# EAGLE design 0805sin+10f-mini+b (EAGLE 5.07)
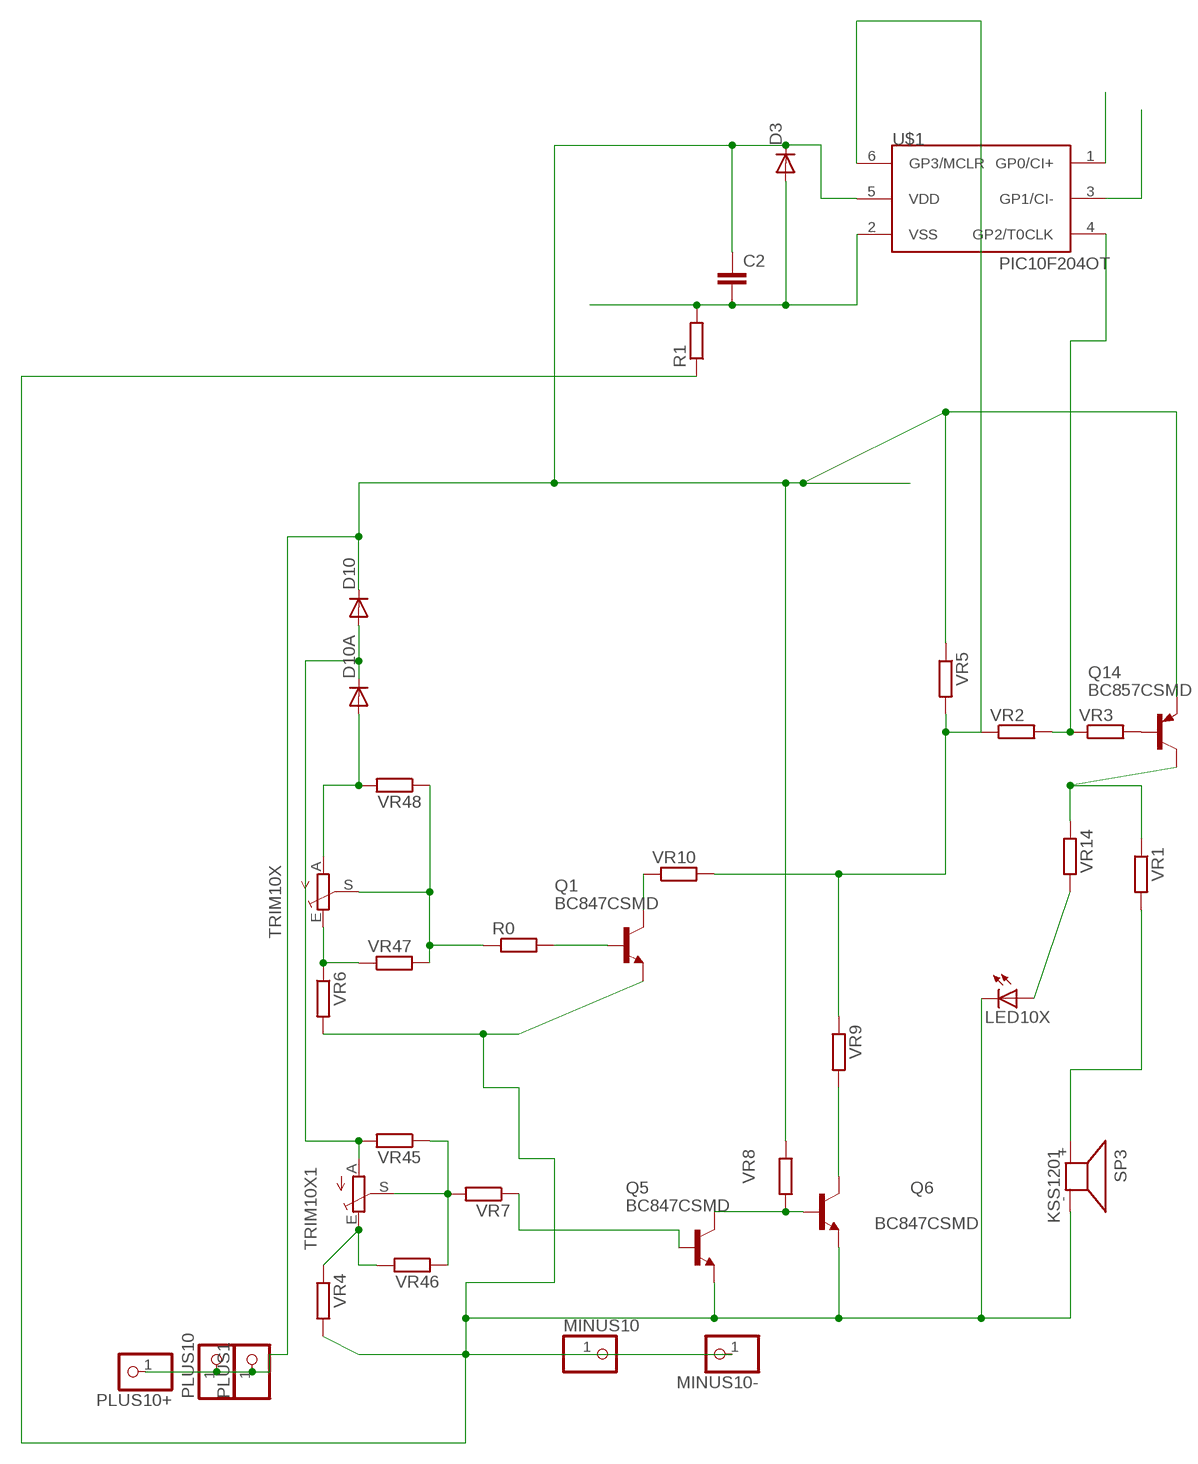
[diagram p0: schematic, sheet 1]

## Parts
C2  C-EUC0805  [C0805]
D3  DIODE-MINIMELF  [MINIMELF]
D10  DIODE-MINIMELF  [MINIMELF]
D10A  DIODE-MINIMELF  [MINIMELF]
LED10X  LEDCHIPLED_1206  [CHIPLED_1206]
MINUS10  PINHD-1X14.5MM  [1X4MM5]
MINUS10-  PINHD-1X11X0.4  [1X01]
PLUS1  PINHD-1X14.5MM  [1X4MM5]
PLUS10  PINHD-1X14.5MM  [1X4MM5]
PLUS10+  PINHD-1X11X0.4  [1X01]
Q1  BC847CSMD  [SOT23]
Q5  BC847CSMD  [SOT23]
Q6  BC847CSMD  [SOT23]
Q14  BC857CSMD  [SOT23-BEC]
R0  R-EU_R0805  [R0805]
R1  R-EU_R0805  [R0805]
SP3  KSS1201  KSS12017MM  [KSS1202]
TRIM10X  TRIM_EU-S64W  [S64W]
TRIM10X1  TRIM_EU-S64W  [S64W]
U$1  PIC10F204OT  [SOT23-6]
VR1  R-EU_R0805  [R0805]
VR2  R-EU_R0805  [R0805]
VR3  R-EU_R1206  [R1206]
VR4  R-EU_R1206  [R1206]
VR5  R-EU_R0805  [R0805]
VR6  R-EU_R1206  [R1206]
VR7  R-EU_M1206  [M1206]
VR8  R-EU_R1206  [R1206]
VR9  R-EU_R0805  [R0805]
VR10  R-EU_R1206  [R1206]
VR14  R-EU_R0805  [R0805]
VR45  R-EU_R1206  [R1206]
VR46  R-EU_R0805  [R0805]
VR47  R-EU_R0805  [R0805]
VR48  R-EU_R0805  [R0805]

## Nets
B: R0.1 TRIM10X.S VR47.2 VR48.1
GP3: U$1.4(GP2/T0CLK) VR2.2 VR3.1
N$1: SP3.+ VR1.2
N$2: Q1.3(C) VR10.1
N$3: Q5.3(C) Q6.1(B) VR8.2
N$4: LED10X.A VR14.2
N$5: Q6.3(C) VR9.2
N$6: U$1.6(GP3/MCLR) VR2.1 VR5.2 VR9.1 VR10.2
N$7: Q1.1(B) R0.2
N$8: Q14.C VR1.1 VR14.1
N$10: Q14.B VR3.2
N$14: D10A.A TRIM10X.A VR48.2
N$17: D10.A D10A.C TRIM10X1.A VR45.2
N$22: TRIM10X1.S VR7.2 VR45.1 VR46.1
N$24: TRIM10X1.E VR4.1 VR46.2
N$128: TRIM10X.E VR6.1 VR47.1
N$138: U$1.1(GP0/CI+)
N$165: U$1.3(GP1/CI-)
N$168: Q5.1(B) VR7.1
PLUS11: C2.1 D3.C D10.C PLUS1.1 PLUS10+.1 PLUS10.1 Q14.E U$1.5(VDD) VR5.1 VR8.1
VSS: LED10X.C MINUS10-.1 MINUS10.1 Q1.2(E) Q5.2(E) Q6.2(E) R1.1 SP3.- VR4.2 VR6.2
VSS1: C2.2 D3.A R1.2 U$1.2(VSS)

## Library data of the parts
C2 = rcl:C-EU: CAPACITOR, European symbol
D3 D10 D10A = diode:DIODE-: DIODE
LED10X = led:LED: LED
MINUS10 MINUS10- PLUS1 PLUS10 PLUS10+ = pinhead:PINHD-1X1: PIN HEADER
Q1 Q5 Q6 = transistor-npn:BC847*: NPN Transistor
Q14 = transistor-pnp:BC857*: PNP Transistror
R0 R1 VR1-VR10 VR14 VR45-VR48 = rcl-2:R-EU_: RESISTOR, European symbol
SP3 = buzzer:KSS1201: SPEAKER
TRIM10X TRIM10X1 = pot:TRIM_EU-: POTENTIOMETER
U$1 = microchip-3:PIC10F2*: uPC nW 0,25/0,5k Program Flash memory Comparator

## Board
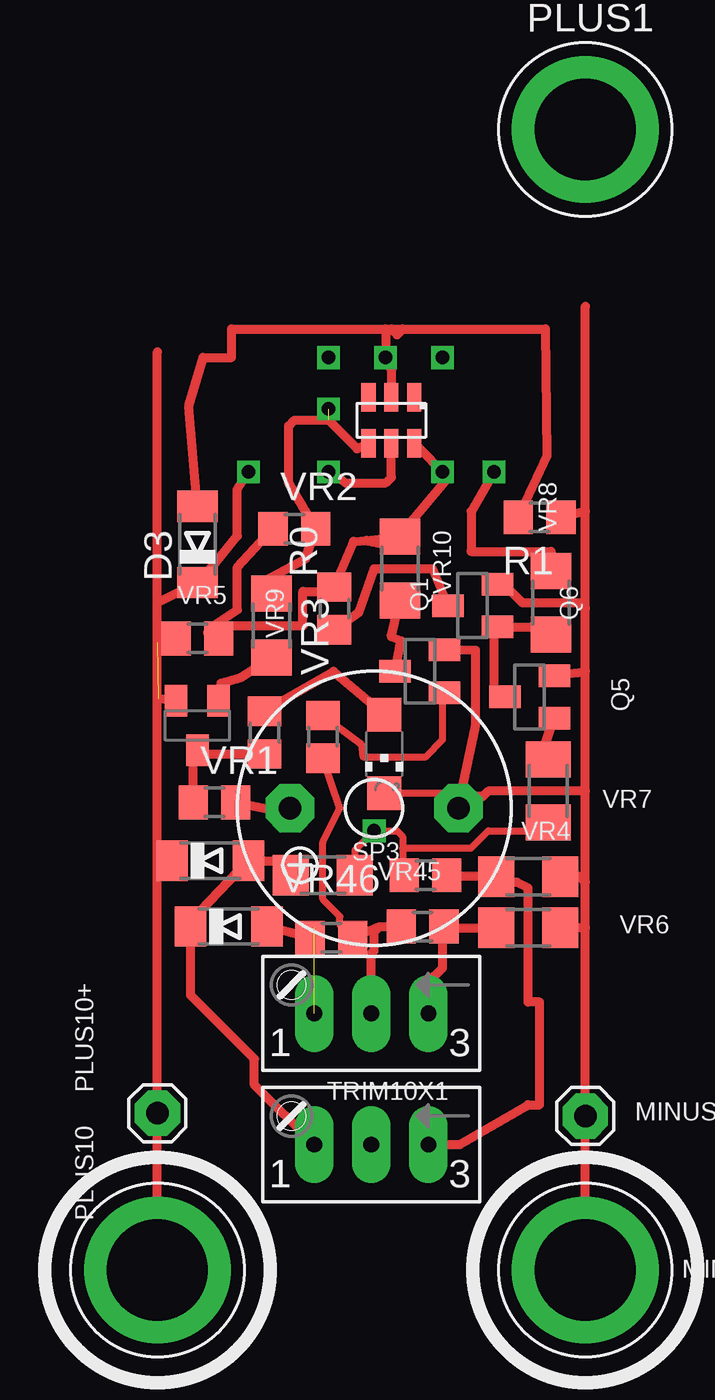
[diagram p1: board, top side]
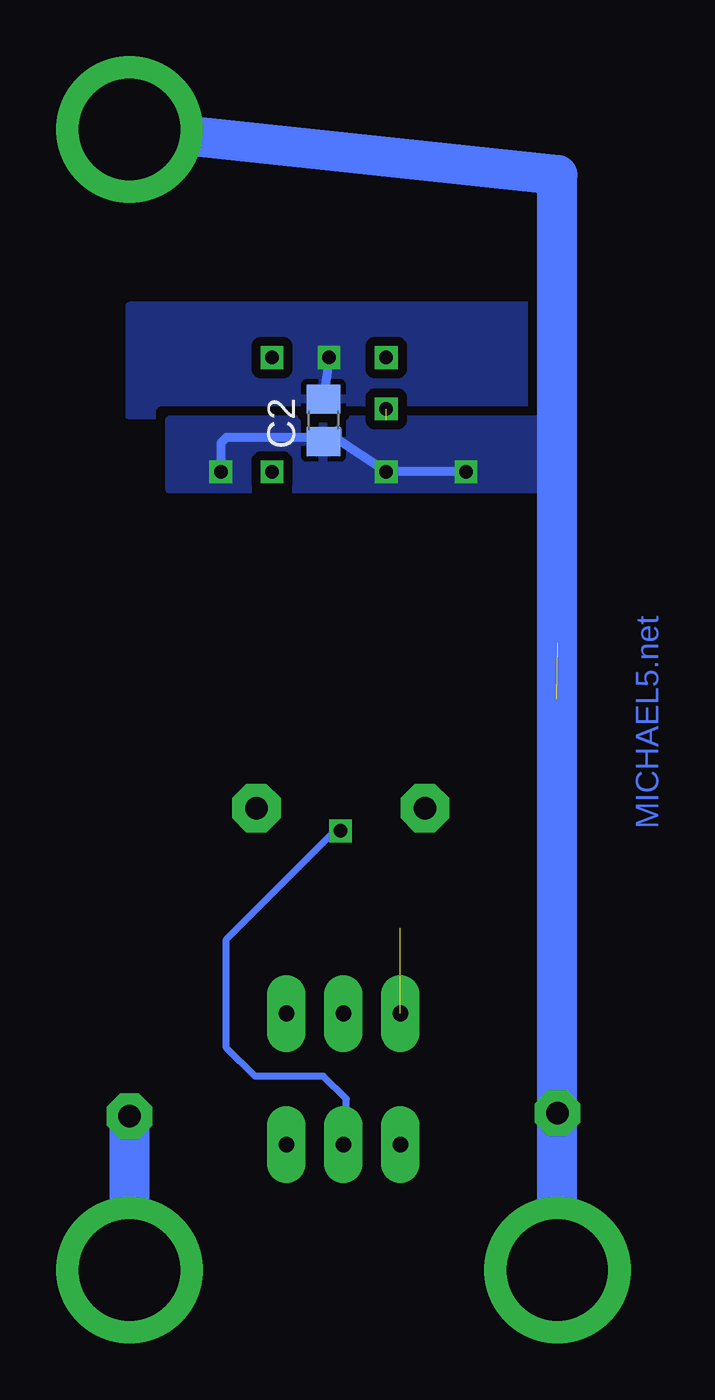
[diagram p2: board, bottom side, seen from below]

No outline drawn. Coordinates in mm, seen from the top.
Copper layers (1*16): Top 0.035mm / dielectric 1.5mm / Bottom 0.035mm
Design rules "default *": minimum track width 8mil, minimum drill 4mil, track to track 8mil, track to pad 8mil, pad to pad 8mil, via to via 8mil, smd to smd 8mil, copper to edge 40mil, drill to drill 8mil, minimum pad ring 20mil, minimum via ring 8mil, stop-mask expansion 4mil, vias tented up to drill 0mil, thermal gap 10mil

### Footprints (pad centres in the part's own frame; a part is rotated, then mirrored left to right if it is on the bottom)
C0805 = smd 1.3 x 1.5: 1 -0.95,0; 2 0.95,0
MINIMELF = smd 1.4 x 1.8: A 1.7,0; C -1.7,0
CHIPLED_1206 = smd 1.5 x 1.5: A 0,-1.75; C 0,1.75
1X4MM5 = drill 4.5 pad 6.35 round: 1 0,0
1X01 = drill 1 pad 1.676 octagon: 1 0,0
SOT23 = smd 1 x 1.4: 1 -0.95,-1.1; 2 0.95,-1.1; 3 0,1.1
SOT23-BEC = smd 1 x 1.4: B -0.95,-1.1; C 0,1.1; E 0.95,-1.1
R0805 = smd 1.3 x 1.5: 1 -0.95,0; 2 0.95,0
KSS1202 = drill 1 pad 2.159 octagon: + 3.75,0; - -3.75,0
S64W = drill 0.7 long: A 2.54,1.27; E -2.54,1.27; S 0,1.27
SOT23-6 = smd 0.635 x 1.27: 1 -1.016,-1.016; 2 0,-1.016; 3 1.016,-1.016; 4 1.016,1.016; 5 0,1.016; 6 -1.016,1.016
R1206 = smd 1.6 x 1.803: 1 -1.422,0; 2 1.422,0
M1206 = smd 1.6 x 2: 1 -1.4,0; 2 1.4,0

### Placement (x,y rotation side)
C2  81.53,46.74 90 bottom
D3  72.9,41.21 90 top
D10  73.47,27.11 0 top
D10A  74.3,24.19 0 top
LED10X  81.22,31.88 180 top
MINUS10  90.17,8.89 0 top
MINUS10-  90.17,15.75 0 top
PLUS1  90.17,59.69 0 top
PLUS10  71.12,8.89 0 top
PLUS10+  71.12,15.88 0 top
Q1  82.8,35.56 90 top
Q5  87.69,34.42 90 top
Q6  85.15,38.48 90 top
Q14  72.9,33.15 180 top
R0  78.49,32.64 90 top
R1  88.14,42.42 180 top
SP3  80.77,29.46 180 top
TRIM10X  80.64,21.59 180 top
TRIM10X1  80.64,15.75 180 top
U$1  81.53,46.74 180 top
VR1  73.66,29.72 0 top
VR2  77.22,41.91 0 top
VR3  76.2,37.59 270 top
VR4  87.63,26.42 0 top
VR5  72.9,37.02 0 top
VR6  87.63,24.13 0 top
VR7  88.52,30.23 270 top
VR8  88.65,38.61 270 top
VR9  78.99,38.35 270 top
VR10  81.92,40.13 90 top
VR14  75.88,32.83 90 top
VR45  78.49,26.48 180 top
VR46  83.06,26.48 0 top
VR47  82.93,24.19 180 top
VR48  78.87,23.69 180 top

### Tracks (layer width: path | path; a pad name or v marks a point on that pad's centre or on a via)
B
  Top 0.305: R0.1 79.25,29.46 78.49,27.94 78.49,25.4 79.25,24.64 79.25,24.25 VR48.1
  Top 0.406: 81.03,24.19 VR48.1 | 81.03,24.19 VR47.2 | TRIM10X.S 80.64,22.99 80.77,23.11 80.77,23.94 81.03,24.19
GP3  (via drill 0.6)  (1 unrouted)
  Top 0.406: U$1.4 80.01,45.47 78.74,46.74 77.22,46.74 76.96,46.48 76.96,43.94 VR2.2 77.72,40.57 75.95,39.62 76.2,39.37 VR3.1
  other vias: 78.74,47.24
N$1
  Top 0.406: VR1.2 76.83,29.28 SP3.+
N$2
  Top 0.406: Q1.3 81.96,36.91 81.53,37.08 VR10.1
N$3
  Top 0.406: Q5.3 86.11,34.78 86.11,37.53 Q6.1 88.3,37.53 VR8.2
N$4
  Top 0.406: VR14.2 78.96,35.56 LED10X.A
N$5
  Top 0.406: VR9.2 80.08,38.17 80.77,40.13 83.36,40.13 Q6.3
N$6
  Top 0.406: U$1.6 84.07,44.2 81.53,41.15 80.42,41.39 | 80.42,41.39 VR10.2 | VR5.2 73.34,37.27 73.66,37.59 | 73.66,37.59 77.6,37.59 77.6,39.12 78.67,39.12 VR9.1 79.86,41.34 80.42,41.39 | VR2.1 74.68,40.2 74.68,38.29 73.66,37.59
N$7
  Top 0.305: R0.2 80.2,32.32 80.26,31.75 83.06,31.75 83.82,32.51 83.82,34.53 Q1.1
N$8
  Top 0.406: VR14.1 73.07,31.88 Q14.C 72.71,31.86 VR1.1
N$9  (via drill 0.6)
  other vias: 83.82,44.45
N$10
  Top 0.406: Q14.B 73.96,35.03 74.84,35.28 VR3.2
N$11  (via drill 0.6)
  other vias: 83.82,49.53
N$14  (1 unrouted)
  Top 0.406: 78.11,24.13 VR48.2 D10A.A
N$17
  Top 0.406: VR45.2 77.6,27.11 D10.A 72.59,24.41 D10A.C 72.59,21.13 75.44,18.29 75.44,17.14 TRIM10X1.A
N$22  (via drill 0.6)
  Top 0.305: VR46.1 82.04,26.48 82.04,27.69 | 82.04,27.69 85.09,27.69 85.85,28.45 88.14,28.45 VR7.2 | VR45.1 79.91,27.58 v80.77,28.45 81.79,28.45 82.04,28.19 82.04,27.69
  Bottom 0.305: v80.77,28.45 81.03,28.45 85.85,23.62 85.85,18.8 84.58,17.53 81.53,17.53 80.52,16.51 80.52,14.61 TRIM10X1.S
N$24
  Top 0.406: TRIM10X1.E 84.58,14.48 87.63,16.26 88.14,16.26 88.14,20.83 87.63,20.83 87.63,25.91 87.12,26.16 86.46,26.16 VR4.1 84.03,26.42 VR46.2
N$128
  Top 0.406: TRIM10X.E 83.19,21.72 83.82,22.35 83.82,24.13 VR47.1 83.82,24.13 VR6.1
N$168
  Top 0.406: Q5.1 88.28,31.99 VR7.1
PLUS11  (via drill 0.6)  (1 unrouted)
  Top 0.406: PLUS10.1 71.12,27.11 | 71.12,27.11 D10.C | Q14.E 71.16,34.33 | VR8.1 88.65,40.89 85.09,40.89 85.09,42.67 v86.11,44.45 | U$1.5 81.53,44.2 81.28,43.94 79.5,43.94 v78.74,44.45 | v75.18,44.45 74.68,43.69 74.68,41.59 73.6,40.26 D3.C 71.12,38.62 | 71.12,27.11 71.12,36.83 | 71.12,36.83 71.12,38.62 | 71.12,38.62 71.12,49.78 | VR5.1 71.31,37.02 71.12,36.83
  Bottom 0.406: v86.11,44.45 86.11,45.72 85.85,45.97 81.03,45.97 | 81.03,45.97 v78.74,44.45 v75.18,44.45 | C2.1 80.91,46.29 80.91,45.9 81.03,45.9 81.03,45.97
  Bottom 1.778: PLUS1.1 71.12,57.66 PLUS10+.1 PLUS10.1
  pour Bottom (isolate 0.406): 70.61,46.74 88.39,46.74 88.39,43.69 70.87,43.69
VDF  (via drill 0.6)
  other vias: 78.74,49.53
VSS
  Top 0.305: LED10X.C 83.86,30.13 SP3.-
  Top 0.406: 90.17,30.23 90.17,35.56 | 90.17,35.56 90.17,38.35 | 90.17,38.35 90.17,42.67 | 90.17,42.67 90.17,51.82 | MINUS10.1 90.17,24.13 | 90.17,24.13 90.17,26.16 | 90.17,26.16 90.17,30.23 | 90.17,30.23 85.85,30.23 85.6,29.97 85.34,29.97 85.34,29.46 SP3.- 85.28,33.15 85.28,36.49 Q1.2 | Q5.2 90.1,35.49 90.17,35.56 | VR4.2 89.92,26.42 90.17,26.16 | 90.17,24.13 VR6.2 | 90.17,42.67 R1.1 | Q6.2 86.55,39.43 87.38,38.61 89.92,38.61 90.17,38.35
  Bottom 1.778: MINUS10.1 MINUS10-.1
VSS1  (via drill 0.6)
  Top 0.406: R1.2 88.46,45.15 88.39,50.8 82.04,50.8 | 81.53,50.8 82.04,50.8 | 81.28,50.8 74.42,50.8 74.42,49.53 73.15,49.53 72.52,47.37 D3.A | 81.28,50.8 81.53,50.8 | 81.53,50.8 81.79,50.55 82.04,50.8 | U$1.2 81.53,48.96 v81.28,49.53 81.28,50.8
  Bottom 0.406: v81.28,49.53 C2.2
  pour Bottom (isolate 0.406, rank 2): 71.88,51.82 90.17,51.82 90.17,46.99 72.14,46.99

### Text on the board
Bottom: MICHAEL5.net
